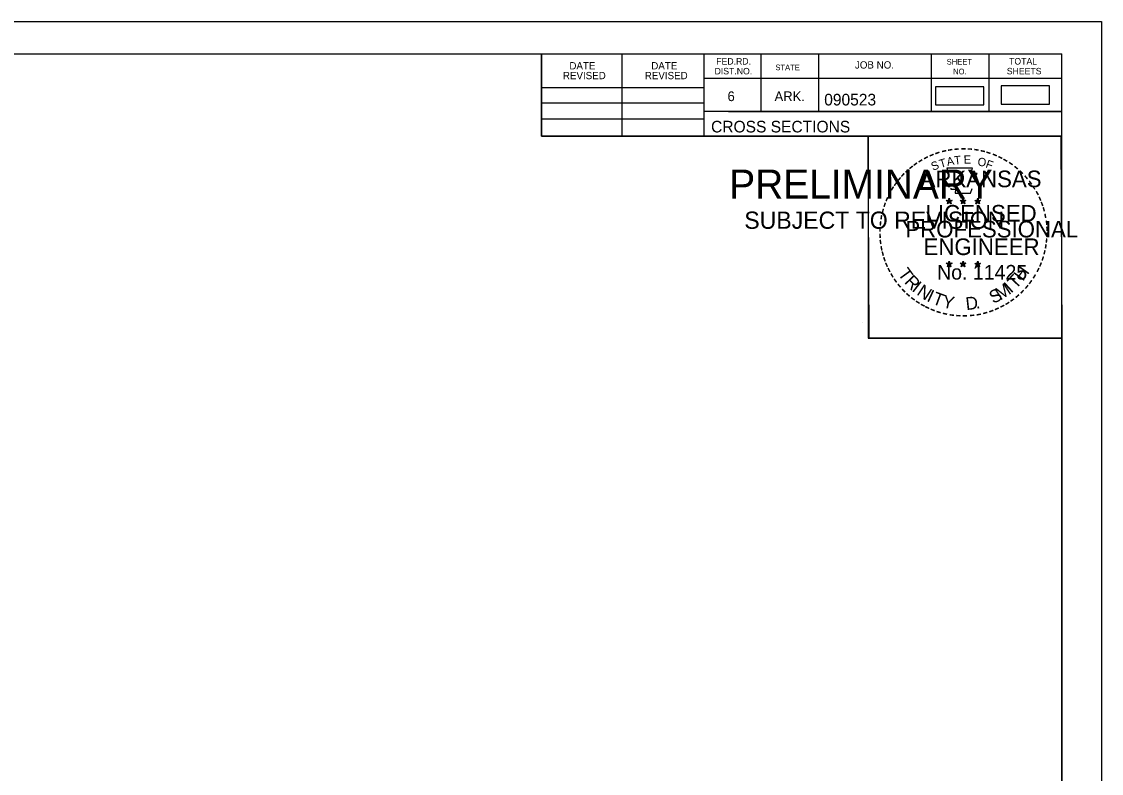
# Model space of a CAD drawing. Extents: x 1406028 to 1412453, y 321733 to 325986.
# Drawn here: x 1406622.8 to 1406752.8, y 325468.9 to 325559.4 of the extents above; entities that cross this region are included whole.
import ezdxf

# ---------------------------------------------------------------- set-up
doc = ezdxf.new("R2010")
doc.units = 0
for name, color, linetype in [('R_Border', 7, 'Continuous'), ('R_Border PE', 7, 'Continuous'), ('R_Border Prem', 7, 'Continuous'), ('R_Fin Surface', 7, 'Continuous'), ('R_No Plot', 7, 'Continuous')]:
    doc.layers.add(name, color=color, linetype=linetype)

msp = doc.modelspace()

# ---------------------------------------------------------------- linework, layer by layer
at = {"layer": 'R_Border'}
for p, q in [((1406431.89, 325555.52), (1406748.07, 325555.52)), ((1406685.43, 325545.64), (1406685.43, 325555.52)), ((1406695.11, 325545.64), (1406695.11, 325555.52)), ((1406704.97, 325555.52), (1406704.97, 325545.64)), ((1406711.81, 325555.52), (1406711.81, 325548.58)), ((1406718.75, 325555.52), (1406718.75, 325548.58)), ((1406732.33, 325555.52), (1406732.33, 325548.58)), ((1406739.27, 325555.52), (1406739.27, 325548.58)), ((1406748.07, 325350.06), (1406748.07, 325555.52)), ((1406748.07, 325552.58), (1406704.97, 325552.58)), ((1406748.07, 325552.6), (1406748.07, 325552.6)), ((1406685.43, 325551.5), (1406704.97, 325551.5)), ((1406685.43, 325549.64), (1406704.97, 325549.64)), ((1406748.07, 325548.58), (1406704.97, 325548.58)), ((1406707.93, 325548.58), (1406748.07, 325548.58)), ((1406685.43, 325547.7), (1406704.97, 325547.7)), ((1406748.07, 325545.64), (1406685.43, 325545.64))]:
    msp.add_line(p, q, dxfattribs=at)
at = {"layer": 'R_Border PE'}
for p, q in [((1406734.15, 325537.89), (1406734.5, 325537.78)), ((1406734.15, 325537.89), (1406734.41, 325537.85)), ((1406734.15, 325537.89), (1406734.39, 325537.77)), ((1406734.29, 325537.49), (1406734.5, 325537.78)), ((1406734.29, 325537.49), (1406734.41, 325537.73)), ((1406734.29, 325537.49), (1406734.5, 325537.7)), ((1406734.5, 325538.15), (1406734.46, 325537.9)), ((1406734.5, 325537.78), (1406734.5, 325538.15)), ((1406734.5, 325538.15), (1406734.55, 325537.9)), ((1406734.85, 325537.89), (1406734.5, 325537.78)), ((1406734.72, 325537.49), (1406734.5, 325537.78)), ((1406734.72, 325537.49), (1406734.5, 325537.7)), ((1406734.85, 325537.89), (1406734.56, 325537.85)), ((1406734.72, 325537.49), (1406734.58, 325537.78)), ((1406734.85, 325537.89), (1406734.65, 325537.79)), ((1406735.82, 325537.89), (1406736.17, 325537.78)), ((1406735.82, 325537.89), (1406736.08, 325537.85)), ((1406735.82, 325537.89), (1406736.06, 325537.77)), ((1406735.96, 325537.49), (1406736.17, 325537.78)), ((1406735.96, 325537.49), (1406736.08, 325537.73)), ((1406735.96, 325537.49), (1406736.17, 325537.7)), ((1406736.17, 325538.15), (1406736.13, 325537.9)), ((1406736.17, 325537.78), (1406736.17, 325538.15)), ((1406736.17, 325538.15), (1406736.22, 325537.9)), ((1406736.52, 325537.89), (1406736.17, 325537.78)), ((1406736.39, 325537.49), (1406736.17, 325537.78)), ((1406736.39, 325537.49), (1406736.17, 325537.7)), ((1406736.52, 325537.89), (1406736.23, 325537.85)), ((1406736.39, 325537.49), (1406736.25, 325537.78)), ((1406736.52, 325537.89), (1406736.32, 325537.79)), ((1406737.59, 325537.88), (1406737.94, 325537.77)), ((1406737.59, 325537.88), (1406737.84, 325537.84)), ((1406737.59, 325537.88), (1406737.83, 325537.76)), ((1406737.72, 325537.47), (1406737.94, 325537.77)), ((1406737.72, 325537.47), (1406737.85, 325537.72)), ((1406737.72, 325537.47), (1406737.94, 325537.69)), ((1406737.94, 325538.14), (1406737.9, 325537.88)), ((1406737.94, 325537.77), (1406737.94, 325538.14)), ((1406737.94, 325538.14), (1406737.99, 325537.89)), ((1406738.28, 325537.88), (1406737.94, 325537.77)), ((1406738.15, 325537.47), (1406737.94, 325537.77)), ((1406738.15, 325537.47), (1406737.94, 325537.69)), ((1406738.28, 325537.88), (1406738, 325537.83)), ((1406738.15, 325537.47), (1406738.01, 325537.77)), ((1406738.28, 325537.88), (1406738.08, 325537.78)), ((1406734.15, 325530.32), (1406734.5, 325530.21)), ((1406734.15, 325530.32), (1406734.4, 325530.28)), ((1406734.15, 325530.32), (1406734.39, 325530.2)), ((1406734.28, 325529.91), (1406734.5, 325530.21)), ((1406734.28, 325529.91), (1406734.41, 325530.16)), ((1406734.28, 325529.91), (1406734.5, 325530.13)), ((1406734.5, 325530.58), (1406734.46, 325530.32)), ((1406734.5, 325530.21), (1406734.5, 325530.58)), ((1406734.5, 325530.58), (1406734.55, 325530.33)), ((1406734.85, 325530.32), (1406734.5, 325530.21)), ((1406734.71, 325529.91), (1406734.5, 325530.21)), ((1406734.71, 325529.91), (1406734.5, 325530.13)), ((1406734.85, 325530.32), (1406734.56, 325530.27)), ((1406734.71, 325529.91), (1406734.58, 325530.2)), ((1406734.85, 325530.32), (1406734.64, 325530.22)), ((1406735.82, 325530.32), (1406736.17, 325530.21)), ((1406735.82, 325530.32), (1406736.07, 325530.28)), ((1406735.82, 325530.32), (1406736.06, 325530.2)), ((1406735.95, 325529.91), (1406736.17, 325530.21)), ((1406735.95, 325529.91), (1406736.08, 325530.16)), ((1406735.95, 325529.91), (1406736.17, 325530.13)), ((1406736.17, 325530.58), (1406736.13, 325530.32)), ((1406736.17, 325530.21), (1406736.17, 325530.58)), ((1406736.17, 325530.58), (1406736.22, 325530.33)), ((1406736.52, 325530.32), (1406736.17, 325530.21)), ((1406736.38, 325529.91), (1406736.17, 325530.21)), ((1406736.38, 325529.91), (1406736.17, 325530.13)), ((1406736.52, 325530.32), (1406736.23, 325530.27)), ((1406736.38, 325529.91), (1406736.24, 325530.2)), ((1406736.52, 325530.32), (1406736.31, 325530.22)), ((1406737.59, 325530.31), (1406737.94, 325530.2)), ((1406737.59, 325530.31), (1406737.84, 325530.27)), ((1406737.59, 325530.31), (1406737.82, 325530.19)), ((1406737.72, 325529.9), (1406737.94, 325530.2)), ((1406737.72, 325529.9), (1406737.85, 325530.15)), ((1406737.72, 325529.9), (1406737.93, 325530.12)), ((1406737.94, 325530.57), (1406737.89, 325530.31)), ((1406738.15, 325529.9), (1406737.93, 325530.12)), ((1406737.94, 325530.2), (1406737.94, 325530.57)), ((1406737.94, 325530.57), (1406737.98, 325530.32)), ((1406738.28, 325530.31), (1406737.94, 325530.2)), ((1406738.15, 325529.9), (1406737.94, 325530.2)), ((1406738.28, 325530.31), (1406738, 325530.26)), ((1406738.15, 325529.9), (1406738.01, 325530.19)), ((1406738.28, 325530.31), (1406738.08, 325530.21))]:
    msp.add_line(p, q, dxfattribs=at)
for points in [[(1406734.2, 325541.77), (1406734.46, 325540.95)], [(1406737.71, 325540.85), (1406737.85, 325541.13), (1406737.16, 325541.11), (1406737.31, 325541.77), (1406734.2, 325541.77)], [(1406734.69, 325539.35), (1406734.69, 325539.26), (1406735.25, 325539.24), (1406735.2, 325538.77), (1406737.07, 325538.77), (1406737.27, 325539.31)], [(1406734.5, 325538.15), (1406734.72, 325537.49), (1406734.15, 325537.89), (1406734.85, 325537.89), (1406734.29, 325537.49), (1406734.5, 325538.15)], [(1406736.17, 325538.15), (1406736.39, 325537.49), (1406735.82, 325537.89), (1406736.52, 325537.89), (1406735.96, 325537.49), (1406736.17, 325538.15)], [(1406737.94, 325538.14), (1406738.15, 325537.47), (1406737.59, 325537.88), (1406738.28, 325537.88), (1406737.72, 325537.47), (1406737.94, 325538.14)], [(1406734.5, 325530.58), (1406734.71, 325529.91), (1406734.15, 325530.32), (1406734.85, 325530.32), (1406734.28, 325529.91), (1406734.5, 325530.58)], [(1406736.17, 325530.58), (1406736.38, 325529.91), (1406735.82, 325530.32), (1406736.52, 325530.32), (1406735.95, 325529.91), (1406736.17, 325530.58)], [(1406737.94, 325530.57), (1406738.15, 325529.9), (1406737.59, 325530.31), (1406738.28, 325530.31), (1406737.72, 325529.9), (1406737.94, 325530.57)]]:
    msp.add_lwpolyline(points, dxfattribs=at)
for centre, radius in [((1406734.5, 325537.78), 0.172), ((1406734.5, 325537.78), 0.145), ((1406734.5, 325537.78), 0.116), ((1406734.5, 325537.78), 0.0991), ((1406734.5, 325537.78), 0.0747), ((1406734.5, 325537.78), 0.0495), ((1406734.5, 325537.78), 0.0296), ((1406736.17, 325537.78), 0.172), ((1406736.17, 325537.78), 0.145), ((1406736.17, 325537.78), 0.116), ((1406736.17, 325537.78), 0.0991), ((1406736.17, 325537.78), 0.0747), ((1406736.17, 325537.78), 0.0495), ((1406736.17, 325537.78), 0.0296), ((1406737.94, 325537.77), 0.172), ((1406737.94, 325537.77), 0.145), ((1406737.94, 325537.77), 0.116), ((1406737.94, 325537.77), 0.0991), ((1406737.94, 325537.77), 0.0747), ((1406737.94, 325537.77), 0.0495), ((1406737.94, 325537.77), 0.0296), ((1406734.5, 325530.21), 0.172), ((1406734.5, 325530.21), 0.145), ((1406734.5, 325530.21), 0.116), ((1406734.5, 325530.21), 0.0991), ((1406734.5, 325530.21), 0.0747), ((1406734.5, 325530.21), 0.0495), ((1406734.5, 325530.21), 0.0296), ((1406736.17, 325530.21), 0.172), ((1406736.17, 325530.21), 0.145), ((1406736.17, 325530.21), 0.116), ((1406736.17, 325530.21), 0.0991), ((1406736.17, 325530.21), 0.0747), ((1406736.17, 325530.21), 0.0495), ((1406736.17, 325530.21), 0.0296), ((1406737.93, 325530.2), 0.172), ((1406737.93, 325530.2), 0.145), ((1406737.93, 325530.2), 0.116), ((1406737.93, 325530.2), 0.0991), ((1406737.93, 325530.2), 0.0747), ((1406737.93, 325530.2), 0.0495), ((1406737.93, 325530.2), 0.0296)]:
    msp.add_circle(centre, radius, dxfattribs=at)
at = {"layer": 'R_Fin Surface'}
for points in [[(1406732.85, 325549.38), (1406738.68, 325549.38), (1406738.68, 325551.57), (1406732.85, 325551.57)], [(1406740.76, 325549.48), (1406746.59, 325549.48), (1406746.59, 325551.67), (1406740.76, 325551.67)]]:
    msp.add_lwpolyline(points, close=True, dxfattribs=at)
at = {"layer": 'R_No Plot'}
for p, q in [((1406419.49, 325559.41), (1406752.82, 325559.41)), ((1406724.1, 325523.18), (1406724.1, 325523.18))]:
    msp.add_line(p, q, dxfattribs=at)
for points in [[(1406419.48, 325559.41), (1406752.82, 325559.41), (1406752.82, 325346.08), (1406419.48, 325346.08)], [(1406665.81, 325555.52), (1406685.43, 325555.52), (1406685.43, 325545.64), (1406701.54, 325545.64), (1406724.74, 325545.64), (1406724.74, 325521.31), (1406748.07, 325521.31), (1406748.07, 325350.06), (1406431.89, 325350.06), (1406431.89, 325555.52)], [(1406724.74, 325545.64), (1406747.95, 325545.64), (1406748.07, 325521.31), (1406724.86, 325521.31)]]:
    msp.add_lwpolyline(points, close=True, dxfattribs=at)

# ---------------------------------------------------------------- texts
at = {"layer": 'R_Border'}
for s, height, p in [('FED.RD.', 0.782, (1406706.45, 325554.24)), ('JOB NO.', 0.879, (1406723.15, 325553.76)), ('SHEET', 0.684, (1406734.19, 325554.24)), ('TOTAL', 0.782, (1406741.71, 325554.24)), ('REVISED', 0.879, (1406687.99, 325552.48)), ('DATE', 0.879, (1406688.77, 325553.66)), ('REVISED', 0.879, (1406697.85, 325552.48)), ('DATE', 0.879, (1406698.63, 325553.66)), ('DIST.NO.', 0.782, (1406706.25, 325553.06)), ('STATE', 0.684, (1406713.57, 325553.56)), ('NO.', 0.684, (1406734.97, 325553.06)), ('SHEETS', 0.782, (1406741.43, 325553.06)), ('6', 1.17, (1406707.81, 325549.84)), ('ARK.', 1.172, (1406713.47, 325549.84)), ('090523', 1.4, (1406719.45, 325549.32)), ('CROSS SECTIONS', 1.4, (1406705.83, 325546.07))]:
    msp.add_text(s, height=height, rotation=360, dxfattribs=at).set_placement(p)
at = {"layer": 'R_Border PE'}
for s, height, rotation, p in [('-', 1.6, 5.8968, (1406735.1, 325543.41)), ('-', 1.6, 0.1862, (1406735.87, 325543.48)), ('-', 1.6, 357.743, (1406736.6, 325543.47)), ('-', 1.6, 34.0636, (1406731.08, 325541.94)), ('-', 1.6, 28.7918, (1406731.68, 325542.31)), ('-', 1.6, 24.3072, (1406732.31, 325542.63)), ('-', 1.6, 19.1761, (1406732.94, 325542.9)), ('T', 1, 16.4036, (1406733.46, 325541.78)), ('-', 1.6, 13.6301, (1406733.69, 325543.14)), ('A', 1, 11.2132, (1406734.29, 325542.03)), ('-', 1.6, 10.2193, (1406734.37, 325543.3)), ('T', 1, 6.0228, (1406735.14, 325542.2)), ('E', 1, 0.8323, (1406736.24, 325542.31)), ('-', 1.6, 352.1617, (1406737.34, 325543.42)), ('O', 1, 350.4515, (1406737.85, 325542.1)), ('-', 1.6, 347.2049, (1406738.06, 325543.3)), ('-', 1.6, 342.3362, (1406738.69, 325543.15)), ('-', 1.6, 337.8551, (1406739.43, 325542.92)), ('-', 1.6, 334.1211, (1406740.06, 325542.65)), ('-', 1.6, 329.6409, (1406740.64, 325542.37)), ('-', 1.6, 42.9622, (1406729.59, 325540.75)), ('-', 1.6, 38.9507, (1406730.03, 325541.17)), ('-', 1.6, 36.2317, (1406730.5, 325541.55)), ('S', 1, 21.594, (1406732.55, 325541.45)), ('F', 1, 340.0707, (1406738.8, 325541.87)), ('-', 1.6, 325.8627, (1406741.28, 325542.01)), ('-', 1.6, 320.5297, (1406741.89, 325541.58)), ('-', 1.6, 50.6142, (1406728.74, 325539.79)), ('-', 1.6, 48.423, (1406729.14, 325540.28)), ('ARKANSAS', 2, 360, (1406731.05, 325539.48)), ('-', 1.6, 315.5786, (1406742.49, 325541.09)), ('-', 1.6, 309.8797, (1406743.06, 325540.54)), ('-', 1.6, 306.6522, (1406743.58, 325539.94)), ('-', 1.6, 58.0706, (1406728, 325538.7)), ('-', 1.6, 54.2325, (1406728.33, 325539.22)), ('-', 1.4, 303.6753, (1406744.07, 325539.37)), ('-', 1.6, 299.6684, (1406744.39, 325538.77)), ('-', 1.6, 67.7743, (1406727.43, 325537.47)), ('-', 1.6, 62.8713, (1406727.69, 325538.08)), ('DWB', 0.01, 360, (1406734.49, 325537.78)), ('DWB', 0.01, 360, (1406736.16, 325537.78)), ('DWB', 0.01, 360, (1406737.92, 325537.77)), ('-', 1.6, 294.6628, (1406744.71, 325538.16)), ('-', 1.6, 290.5728, (1406744.97, 325537.58)), ('-', 1.6, 75.461, (1406727.02, 325536.13)), ('-', 1.6, 72.3945, (1406727.21, 325536.84)), ('LICENSED', 2, 360, (1406731.65, 325535.34)), ('-', 1.6, 285.1233, (1406745.2, 325537)), ('-', 1.6, 85.1863, (1406726.81, 325534.72)), ('-', 1.6, 81.2013, (1406726.88, 325535.41)), ('PROFESSIONAL', 2, 360, (1406729.22, 325533.43)), ('-', 1.6, 280.5493, (1406745.4, 325536.26)), ('-', 1.6, 276.5962, (1406745.57, 325535.49)), ('-', 1.6, 94.1959, (1406726.82, 325533.3)), ('-', 1.6, 89.0622, (1406726.78, 325534.02)), ('-', 1.6, 274.3301, (1406745.63, 325534.77)), ('-', 1.6, 269.9407, (1406745.66, 325534.13)), ('-', 1.6, 98.9479, (1406726.89, 325532.63)), ('ENGINEER', 2, 360, (1406731.41, 325531.31)), ('-', 1.6, 260.9953, (1406745.57, 325532.81)), ('-', 1.6, 263.5172, (1406745.64, 325533.47)), ('-', 1.6, 101.7149, (1406727.02, 325531.9)), ('-', 1.6, 105.4578, (1406727.19, 325531.3)), ('-', 1.6, 252.8681, (1406745.28, 325531.42)), ('-', 1.6, 255.7626, (1406745.46, 325532.14)), ('-', 1.6, 109.0874, (1406727.4, 325530.67)), ('-', 1.6, 114.0643, (1406727.66, 325530.07)), ('T', 1.54, 306.0406, (1406728.26, 325529.05)), ('No. 11425', 1.757, 360, (1406733.04, 325528.36)), ('DWB', 0.01, 360, (1406734.49, 325530.21)), ('DWB', 0.01, 360, (1406736.16, 325530.21)), ('DWB', 0.01, 360, (1406737.92, 325530.2)), ('H', 1.54, 54.6088, (1406743.38, 325528.08)), ('-', 1.6, 247.8887, (1406745.06, 325530.74)), ('-', 1.6, 115.7289, (1406727.96, 325529.46)), ('-', 1.6, 120.4471, (1406728.32, 325528.87)), ('R', 1.54, 314.005, (1406729.02, 325528)), ('T', 1.54, 46.6444, (1406742.49, 325527.14)), ('-', 1.6, 239.0712, (1406744.4, 325529.36)), ('-', 1.6, 244.6197, (1406744.79, 325530.11)), ('-', 1.6, 125.8934, (1406728.72, 325528.31)), ('-', 1.6, 130.7181, (1406729.18, 325527.76)), ('-', 1.6, 134.2238, (1406729.7, 325527.21)), ('I', 1.54, 321.9694, (1406729.92, 325527.07)), ('N', 1.54, 326.5002, (1406730.49, 325526.6)), ('M', 1.54, 32.6563, (1406740.64, 325525.82)), ('I', 1.54, 42.1136, (1406741.93, 325526.66)), ('-', 1.6, 231.2538, (1406743.57, 325528.14)), ('-', 1.6, 233.8452, (1406744, 325528.71)), ('-', 1.6, 138.9338, (1406730.22, 325526.75)), ('-', 1.6, 144.6463, (1406730.78, 325526.34)), ('I', 1.54, 335.3603, (1406731.7, 325525.81)), ('T', 1.54, 339.8912, (1406732.36, 325525.48)), ('Y', 1.54, 347.8556, (1406733.58, 325525.04)), ('D', 1.54, 6.3969, (1406736.56, 325524.68)), ('S', 1.54, 26.9312, (1406739.8, 325525.41)), ('-', 1.6, 215.7363, (1406742.02, 325526.6)), ('-', 1.6, 221.0851, (1406742.57, 325527.07)), ('-', 1.6, 225.7653, (1406743.09, 325527.58)), ('-', 1.6, 148.0898, (1406731.34, 325525.97)), ('-', 1.6, 151.5704, (1406731.92, 325525.65)), ('-', 1.6, 154.6002, (1406732.44, 325525.4)), ('-', 1.6, 158.5612, (1406733.07, 325525.15)), ('.', 1.54, 13.7642, (1406737.75, 325524.81)), ('-', 1.6, 200.7184, (1406739.68, 325525.27)), ('-', 1.6, 204.2516, (1406740.3, 325525.55)), ('-', 1.6, 207.3568, (1406740.93, 325525.87)), ('-', 1.6, 212.2491, (1406741.48, 325526.21)), ('-', 1.6, 162.7983, (1406733.75, 325524.93)), ('-', 1.6, 167.5555, (1406734.47, 325524.77)), ('-', 1.6, 173.1155, (1406735.24, 325524.66)), ('-', 1.6, 176.5183, (1406735.99, 325524.61)), ('-', 1.6, 181.5918, (1406736.73, 325524.62)), ('-', 1.6, 185.8167, (1406737.54, 325524.7)), ('-', 1.6, 191.2858, (1406738.28, 325524.83)), ('-', 1.6, 195.4743, (1406739.01, 325525.03))]:
    msp.add_text(s, height=height, rotation=rotation, dxfattribs=at).set_placement(p)
at = {"layer": 'R_Border Prem'}
for s, height, p in [('PRELIMINARY', 3.5, (1406708.02, 325538.1)), ('DWB', 0.01, (1406708.77, 325539.95)), ('SUBJECT TO REVISION', 2.0751, (1406709.83, 325534.47))]:
    msp.add_text(s, height=height, rotation=360, dxfattribs=at).set_placement(p)

doc.saveas('drawing.dxf')
